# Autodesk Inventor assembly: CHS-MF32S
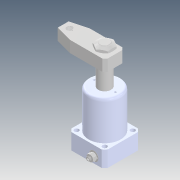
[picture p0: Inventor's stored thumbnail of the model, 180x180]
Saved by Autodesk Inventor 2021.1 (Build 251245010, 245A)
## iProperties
Created: 2020-02
Part Number: CHS-MF32S
Description: STEP AP214
Document SubType Name: Assembly
Designer: user
Title: chs-mf32s_asm.STEP
Revision Number: ÈÎºÎ
Sending System: SolidWorks 2016
Preprocessor: SwSTEP 2.0
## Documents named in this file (9)
- D:\Vault_2016\Projekty\Clamptek\Hydraulic\CHS\CHS-32\Inventor\CHS-MF32S\CHS-MF32S.iam
- D:\Vault_2016\Projekty\Clamptek\Hydraulic\CHS\CHS-32\Inventor\CHS-MF32S\CHS-32S-02_5_1.ipt
- D:\Vault_2016\Projekty\Clamptek\Hydraulic\CHS\CHS-32\Inventor\CHS-MF32S\CHS-32S-01_6.ipt
- D:\Vault_2016\Projekty\Clamptek\Hydraulic\CHS\CHS-32\Inventor\CHS-MF32S\M16_6.ipt
- D:\Vault_2016\Projekty\Clamptek\Hydraulic\CHS\CHS-32\Inventor\CHS-MF32S\CHS-TXF-01_1.ipt
- D:\Vault_2016\Projekty\Clamptek\Hydraulic\CHS\CHS-32\Inventor\CHS-MF32S\CHS-MF32-TXF-02_1.ipt
- D:\Vault_2016\Projekty\Clamptek\Hydraulic\CHS\CHS-32\Inventor\CHS-MF32S\CHS-MF32-TXF-03_1.ipt
- D:\Vault_2016\Projekty\Clamptek\Hydraulic\CHS\CHS-32\Inventor\CHS-MF32S\M6_1.ipt
- D:\Vault_2016\Projekty\Clamptek\Hydraulic\CHS\CHS-32\Inventor\CHS-MF32S\CHS-MF32BT.ipt
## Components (8 placed, 8 different names)
1. CHS-32S-02_5_1_1
2. CHS-32S-01_6_2
3. M16_6_3
4. CHS-TXF-01_1_4
5. CHS-MF32-TXF-02_1_5
6. CHS-MF32-TXF-03_1_6
7. M6_1_7
8. CHS-MF32BT_8
